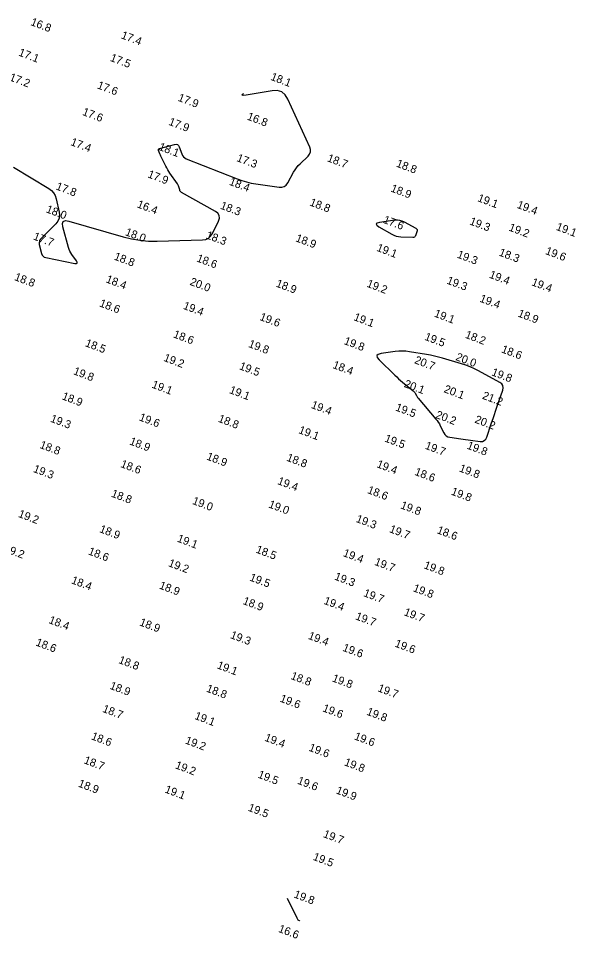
# Model space of a CAD drawing. Extents: x 824616 to 827440, y 158441 to 163197.
# Drawn here: x 827092 to 827440, y 159449 to 160024 of the extents above; entities that cross this region are included whole.
import ezdxf

# ---------------------------------------------------------------- set-up
doc = ezdxf.new("R2010")
doc.units = 0
for name, color, linetype in [('V-CHAN-CONT-EL18', 7, 'Continuous'), ('V-CHAN-CONT-EL20', 7, 'Continuous'), ('V-TOPO-SOUN', 7, 'Continuous')]:
    doc.layers.add(name, color=color, linetype=linetype)

msp = doc.modelspace()

# ---------------------------------------------------------------- linework, layer by layer
at = {"layer": 'V-CHAN-CONT-EL18'}
for points in [[(827089.38, 159931.26), (827111.36, 159917.94), (827113.02, 159916.71), (827114.34, 159915.23), (827115.32, 159913.51), (827115.96, 159911.54), (827117.83, 159903.17), (827118.06, 159901.15), (827117.78, 159899.27), (827117.02, 159897.53), (827115.76, 159895.93), (827106.05, 159886.06), (827105.87, 159885.85), (827105.73, 159885.63), (827105.62, 159885.39), (827105.55, 159885.13), (827105.32, 159884.06), (827105.28, 159883.79), (827105.27, 159883.52), (827105.29, 159883.26), (827105.34, 159882.99), (827106.83, 159877.28), (827107.2, 159876.34), (827107.77, 159875.61), (827108.53, 159875.09), (827109.48, 159874.77), (827127.62, 159871.12), (827128.59, 159871.04), (827129.08, 159871.26), (827129.09, 159871.8), (827128.62, 159872.65), (827125.77, 159876.67), (827125.11, 159877.7), (827124.54, 159878.78), (827124.07, 159879.9), (827123.7, 159881.06), (827120.17, 159893.91), (827119.87, 159896.04), (827120.38, 159897.36), (827121.7, 159897.85), (827123.83, 159897.53), (827157.76, 159887.74), (827163.01, 159886.44), (827168.31, 159885.56), (827173.66, 159885.08), (827179.06, 159885.02), (827207.33, 159885.78), (827209.34, 159886.08), (827211.05, 159886.84), (827212.44, 159888.08), (827213.54, 159889.79), (827217.31, 159897.56), (827217.9, 159899.4), (827217.78, 159901.01), (827216.96, 159902.4), (827215.43, 159903.58), (827194.31, 159915.5), (827193.9, 159915.78), (827193.56, 159916.13), (827193.3, 159916.53), (827193.12, 159917), (827192.55, 159918.98), (827192.38, 159919.47), (827192.18, 159919.94), (827191.95, 159920.39), (827191.67, 159920.82), (827187, 159927.52), (827186.3, 159928.56), (827185.65, 159929.64), (827185.03, 159930.73), (827184.46, 159931.86), (827181.63, 159937.71), (827181.4, 159938.19), (827181.18, 159938.67), (827180.96, 159939.16), (827180.75, 159939.65), (827179.92, 159941.61), (827179.81, 159942.05), (827179.87, 159942.41), (827180.11, 159942.68), (827180.53, 159942.86), (827189.9, 159945.39), (827190.91, 159945.52), (827191.74, 159945.3), (827192.39, 159944.74), (827192.85, 159943.83), (827194.36, 159939.52), (827194.82, 159938.53), (827195.46, 159937.7), (827196.26, 159937.03), (827197.24, 159936.52), (827228.98, 159923.9), (827231.85, 159922.86), (827234.77, 159921.98), (827237.73, 159921.29), (827240.74, 159920.76), (827255.3, 159918.66), (827256.99, 159918.63), (827258.45, 159919.07), (827259.68, 159919.98), (827260.67, 159921.35), (827264.28, 159928), (827265.15, 159929.47), (827266.12, 159930.86), (827267.2, 159932.17), (827268.37, 159933.4), (827273.29, 159938.18), (827274.28, 159939.42), (827274.78, 159940.75), (827274.8, 159942.17), (827274.33, 159943.68), (827260.75, 159973.66), (827259.03, 159976.4), (827256.82, 159978.19), (827254.09, 159979.03), (827250.86, 159978.91), (827234.59, 159976.16), (827232.81, 159975.98), (827232.1, 159976.22), (827232.45, 159976.88), (827232.92, 159977.23)], [(827268.13, 159460.65), (827267.99, 159460.57), (827267.22, 159460.96), (827266.46, 159462.12), (827260.4, 159474.41)]]:
    msp.add_lwpolyline(points, dxfattribs=at)
msp.add_lwpolyline([(827328.29, 159888.2), (827329.71, 159887.88), (827331.18, 159887.74), (827338.82, 159887.41), (827339.42, 159887.46), (827339.91, 159887.68), (827340.3, 159888.05), (827340.58, 159888.58), (827341.5, 159891.02), (827341.63, 159891.59), (827341.56, 159892.09), (827341.29, 159892.52), (827340.82, 159892.87), (827333.52, 159896.93), (827332.09, 159897.59), (827330.61, 159897.99), (827329.09, 159898.14), (827327.51, 159898.04), (827318.02, 159896.68), (827316.46, 159896.3), (827315.85, 159895.73), (827316.2, 159894.98), (827317.51, 159894.04), (827325.61, 159889.36), (827326.93, 159888.69)], close=True, dxfattribs=at)
at = {"layer": 'V-CHAN-CONT-EL20'}
msp.add_lwpolyline([(827352.34, 159813.19), (827349.84, 159813.72), (827347.32, 159814.18), (827336.57, 159815.95), (827334.36, 159816.23), (827332.15, 159816.34), (827329.94, 159816.28), (827327.73, 159816.04), (827318.88, 159814.76), (827317.14, 159814.29), (827316.36, 159813.5), (827316.53, 159812.4), (827317.65, 159810.99), (827327.5, 159801.31), (827328.65, 159800.2), (827329.84, 159799.11), (827331.04, 159798.05), (827332.27, 159797.02), (827339.03, 159791.45), (827339.36, 159791.16), (827339.65, 159790.83), (827339.92, 159790.47), (827340.15, 159790.09), (827341, 159788.51), (827341.22, 159788.12), (827341.47, 159787.74), (827341.73, 159787.38), (827342.01, 159787.03), (827353.14, 159773.9), (827353.93, 159772.92), (827354.65, 159771.9), (827355.31, 159770.83), (827355.91, 159769.72), (827358.17, 159765.21), (827358.82, 159764.2), (827359.64, 159763.42), (827360.63, 159762.88), (827361.8, 159762.57), (827368.68, 159761.52), (827370.2, 159761.29), (827371.72, 159761.08), (827373.24, 159760.88), (827374.77, 159760.69), (827380.87, 159759.95), (827382.27, 159759.97), (827383.41, 159760.41), (827384.28, 159761.25), (827384.9, 159762.5), (827387.69, 159770.86), (827388.08, 159772.03), (827388.47, 159773.19), (827388.86, 159774.35), (827389.25, 159775.52), (827390.82, 159780.17), (827391.22, 159781.33), (827391.62, 159782.49), (827392.01, 159783.65), (827392.42, 159784.81), (827394.92, 159792.02), (827395.22, 159793.5), (827395.01, 159794.79), (827394.29, 159795.89), (827393.06, 159796.78), (827379.8, 159803.95), (827377.21, 159805.26), (827374.57, 159806.43), (827371.86, 159807.47), (827369.1, 159808.37), (827357.29, 159811.88), (827354.83, 159812.57)], close=True, dxfattribs=at)

# ---------------------------------------------------------------- texts
at = {"layer": 'V-TOPO-SOUN'}
for s, p in [('16.8 ', (827099.6, 160020.08)), ('17.4 ', (827156.13, 160011.81)), ('17.1 ', (827092.03, 160001.03)), ('17.5 ', (827149.27, 159997.72)), ('17.2 ', (827086.33, 159985.54)), ('18.1 ', (827249.52, 159985.87)), ('17.6 ', (827141.2, 159980.56)), ('17.9 ', (827191.62, 159972.8)), ('17.6 ', (827131.93, 159963.96)), ('16.8 ', (827234.79, 159961.06)), ('17.9 ', (827185.82, 159957.77)), ('17.4 ', (827124.56, 159945.13)), ('18.1 ', (827179.59, 159942.12)), ('17.3 ', (827228.3, 159935.12)), ('18.7 ', (827284.85, 159935.05)), ('18.8 ', (827327.95, 159931.69)), ('17.9 ', (827172.74, 159924.97)), ('17.8 ', (827115.39, 159917.42)), ('18.4 ', (827223.63, 159920.33)), ('18.9 ', (827324.54, 159916.14)), ('19.1 ', (827378.79, 159910.12)), ('16.4 ', (827166.06, 159906.23)), ('18.3 ', (827218.06, 159905.39)), ('18.8 ', (827273.91, 159907.44)), ('19.4 ', (827403.4, 159905.91)), ('18.0 ', (827109.24, 159903.13)), ('17.6 ', (827319.84, 159896.57)), ('19.3 ', (827373.81, 159895.6)), ('19.2 ', (827398.27, 159891.75)), ('19.1 ', (827427.83, 159892.18)), ('17.7 ', (827101.25, 159886.18)), ('18.0 ', (827158.67, 159888.87)), ('18.3 ', (827209.11, 159886.92)), ('18.9 ', (827265.11, 159885.05)), ('19.1 ', (827315.73, 159879.07)), ('19.3 ', (827365.98, 159874.84)), ('18.3 ', (827392.13, 159876.15)), ('19.6 ', (827421.16, 159877.07)), ('18.8 ', (827151.71, 159873.63)), ('18.6 ', (827203.28, 159872.48)), ('18.8 ', (827089.46, 159860.83)), ('18.4 ', (827146.62, 159859.41)), ('20.0 ', (827199.1, 159857.84)), ('19.3 ', (827359.52, 159858.62)), ('19.4 ', (827386.07, 159862.28)), ('19.4 ', (827412.51, 159857.6)), ('18.9 ', (827252.85, 159856.74)), ('19.2 ', (827309.55, 159856.64)), ('19.4 ', (827380.09, 159847.33)), ('18.6 ', (827142.57, 159844.39)), ('19.4 ', (827194.87, 159842.85)), ('19.6 ', (827242.67, 159835.89)), ('19.1 ', (827301.42, 159835.78)), ('19.1 ', (827351.69, 159838.02)), ('18.9 ', (827403.95, 159838.07)), ('18.6 ', (827188.69, 159825.05)), ('19.5 ', (827345.67, 159823.5)), ('18.2 ', (827371.02, 159824.77)), ('18.5 ', (827133.67, 159819.52)), ('19.8 ', (827235.64, 159819.04)), ('19.8 ', (827295.33, 159820.85)), ('18.6 ', (827393.64, 159815.66)), ('19.2 ', (827182.68, 159810.34)), ('18.4 ', (827288.29, 159805.88)), ('20.7 ', (827339.37, 159808.89)), ('20.0 ', (827365.15, 159810.85)), ('19.8 ', (827126.27, 159802.01)), ('19.5 ', (827229.93, 159805.14)), ('19.8 ', (827387.5, 159801.35)), ('20.1 ', (827332.9, 159794.05)), ('19.1 ', (827175.3, 159793.63)), ('19.1 ', (827223.72, 159790.23)), ('20.1 ', (827357.75, 159790.79)), ('18.9 ', (827119.18, 159786.34)), ('21.2 ', (827381.73, 159786.71)), ('19.4 ', (827274.83, 159780.94)), ('19.5 ', (827327.48, 159779.37)), ('19.3 ', (827111.93, 159772.34)), ('19.6 ', (827167.37, 159773.19)), ('18.8 ', (827216.75, 159772.32)), ('20.2 ', (827352.59, 159774.72)), ('20.2 ', (827377.01, 159771.78)), ('19.1 ', (827266.98, 159765.24)), ('19.5 ', (827320.72, 159760)), ('18.8 ', (827105.29, 159755.96)), ('18.9 ', (827161.39, 159758.17)), ('19.7 ', (827345.97, 159755.47)), ('19.8 ', (827372.13, 159755.53)), ('18.9 ', (827209.48, 159748.74)), ('18.6 ', (827155.79, 159744.05)), ('18.8 ', (827259.47, 159747.98)), ('19.4 ', (827315.77, 159743.94)), ('19.3 ', (827101.23, 159740.97)), ('18.6 ', (827339.47, 159739.14)), ('19.8 ', (827367.31, 159741.32)), ('19.4 ', (827253.82, 159733.39)), ('18.8 ', (827149.95, 159725.53)), ('18.6 ', (827309.96, 159727.77)), ('19.8 ', (827362.27, 159726.84)), ('19.0 ', (827200.61, 159721.01)), ('19.0 ', (827248.23, 159718.82)), ('19.8 ', (827330.68, 159718.25)), ('19.2 ', (827091.88, 159712.87)), ('19.3 ', (827302.84, 159709.77)), ('18.9 ', (827142.59, 159703.39)), ('19.7 ', (827323.7, 159703.38)), ('18.6 ', (827353.41, 159702.71)), ('19.1 ', (827191.13, 159697.46)), ('19.2 ', (827082.84, 159691.24)), ('18.5 ', (827240.3, 159690.6)), ('18.6 ', (827135.59, 159689.48)), ('19.4 ', (827294.76, 159688.42)), ('19.2 ', (827185.62, 159682.13)), ('19.7 ', (827314.41, 159682.93)), ('19.8 ', (827345.25, 159680.8)), ('19.3 ', (827289.4, 159673.75)), ('18.4 ', (827125, 159671.41)), ('18.9 ', (827179.9, 159668.17)), ('19.5 ', (827236.37, 159673.16)), ('19.7 ', (827307.51, 159663.42)), ('19.8 ', (827338.48, 159666.47)), ('18.9 ', (827232.17, 159658.5)), ('19.4 ', (827282.74, 159658.59)), ('19.7 ', (827332.8, 159651.51)), ('18.4 ', (827110.93, 159646.58)), ('18.9 ', (827167.6, 159645.16)), ('19.7 ', (827302.49, 159648.91)), ('19.3 ', (827224.34, 159637.2)), ('19.4 ', (827272.97, 159636.73)), ('18.6 ', (827102.79, 159632.59)), ('19.6 ', (827294.48, 159629.28)), ('19.6 ', (827327.11, 159631.89)), ('18.8 ', (827154.54, 159621.61)), ('19.1 ', (827216.03, 159618.32)), ('18.8 ', (827262.1, 159611.67)), ('19.8 ', (827287.94, 159610.18)), ('18.9 ', (827149.05, 159605.52)), ('18.8 ', (827209.33, 159603.78)), ('19.7 ', (827316.44, 159603.99)), ('19.6 ', (827255.32, 159597.53)), ('18.7 ', (827144.49, 159591.1)), ('19.6 ', (827281.98, 159591.47)), ('19.8 ', (827309.48, 159589.33)), ('19.1 ', (827202.04, 159586.7)), ('18.6 ', (827137.46, 159573.98)), ('19.2 ', (827196.16, 159571.39)), ('19.4 ', (827245.76, 159573.1)), ('19.6 ', (827301.78, 159573.93)), ('19.6 ', (827273.38, 159566.86)), ('18.7 ', (827132.87, 159559.02)), ('19.2 ', (827189.93, 159555.88)), ('19.8 ', (827295.51, 159557.74)), ('19.5 ', (827241.55, 159550.04)), ('18.9 ', (827129.3, 159544.45)), ('19.6 ', (827266.25, 159546.24)), ('19.1 ', (827183.42, 159540.8)), ('19.9 ', (827290.38, 159540.18)), ('19.5 ', (827235.44, 159529.37)), ('19.7 ', (827282.36, 159512.92)), ('19.5 ', (827275.99, 159498.71)), ('19.8 ', (827264.05, 159475.23)), ('16.6 ', (827254.33, 159453.71))]:
    msp.add_text(s, height=5, rotation=339.2, dxfattribs=at).set_placement(p)

doc.saveas('drawing.dxf')
